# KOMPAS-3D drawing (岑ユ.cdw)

Referenced files: Shtamp_v.cdw
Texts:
  Штамп для двух- угловой гибки
  http://freecads.ru/
  Текст на чертеже
  Размерные надписи
  Шероховатость
  Линия-выноска #1
  Линия-выноска #2
  Линия-выноска #3
  Отклонения формы и база
  Заголовок таблицы
  Ячейка таблицы
  Стрелка вида
  Обозначение изменения
  Фигурная скобка
  Номер узла
  Марка координационной оси
  VRCB
  Выносная надпись
  Обозначение узла
  Марка/позиционное обозначение с линией-выноской
  Марка/позиционное обозначение на линии
  Марка/позиционное обозначение без линии-выноски
  Документация
  СГАУ гр.1403
  Штамп для двух-
  угловой гибки
  Сборочный чертеж
  Детали
  Плита накладная
  Матрица
  Прижим
  Пуансон
  Планка фиксирующая
  Плита верхняя ГОСТ 13112-83
  Плита нижняя ГОСТ 13112-83
  Хвостовик ГОСТ 16715-71
  ГОСТ 13120-83
  Штифт 8 х 75 ГОСТ 3128-70
  Втулка направляющая
  Громова Е.Г.
  Штифт 8 х 95 ГОСТ 3128-70
  левая
  правая
  Стандартные изделия
  Винт М4 х 14 ГОСТ 1491-80
  Винт М8 х 90 ГОСТ 1491-80
  Винт М8 х 70 ГОСТ 1491-80
  Колонкака направляющая
Dimensions and other numbers on the sheet: 03ПК01.6512.002.000.801; 7; 1; 2; 3; 4; 5; 6; 8; 9; 10; 11; 15; 12; 16; 17; 13; 14; 18; 103ПК01.6512.002.000.СБ; 103ПК01.6512.002.001; 103ПК01.6512.002.002; 103ПК01.6512.002.003; 103ПК01.6512.002.004; 103ПК01.6512.002.005; 103ПК01.6512.002.006; 103ПК01.6512.002.007; 103ПК01.6512.002.008; 03ПК01.6512.002.000.801-; 0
